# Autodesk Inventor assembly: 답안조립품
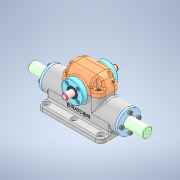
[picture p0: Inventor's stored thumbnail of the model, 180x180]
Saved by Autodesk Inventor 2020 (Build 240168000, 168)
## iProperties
Created: 2024-08
Part Number: 답안조립품
Document SubType Name: Assembly
Designer: oem
Mass: 1366.24 g
Surface Area: 1436.4 cm^2
Volume: 418.392 cm^3
Density: 3.26545 g/cm^3
Author: oem
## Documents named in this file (13)
- C:\Users\oem\Desktop\640804V1002\답안조립품.iam
- C:\Users\oem\Desktop\640804V1002\본체.ipt
- C:\Users\oem\Desktop\640804V1002\오일레스 부시.ipt
- C:\Users\oem\Desktop\640804V1002\부시 커버.ipt
- C:\Users\oem\Desktop\640804V1002\스프링 와셔 M4.ipt
- C:\Users\oem\Desktop\640804V1002\육각 소켓 머리 볼트 M4x10.ipt
- C:\Users\oem\Desktop\640804V1002\랙.ipt
- C:\Users\oem\Desktop\640804V1002\깊은 홈 볼 베어링 6901.ipt
- C:\Users\oem\Desktop\640804V1002\칼라.ipt
- C:\Users\oem\Desktop\640804V1002\피니언.ipt
- C:\Users\oem\Desktop\640804V1002\윗커버.ipt
- C:\Users\oem\Desktop\640804V1002\베어링 커버.ipt
- C:\Users\oem\Desktop\640804V1002\오일실 12 22 7.ipt
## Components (1 placed, 1 different names)
1. 피니언:1 — 각도:2
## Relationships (1: Angle 1)
- 각도:2 [Angle]: 피니언:1
